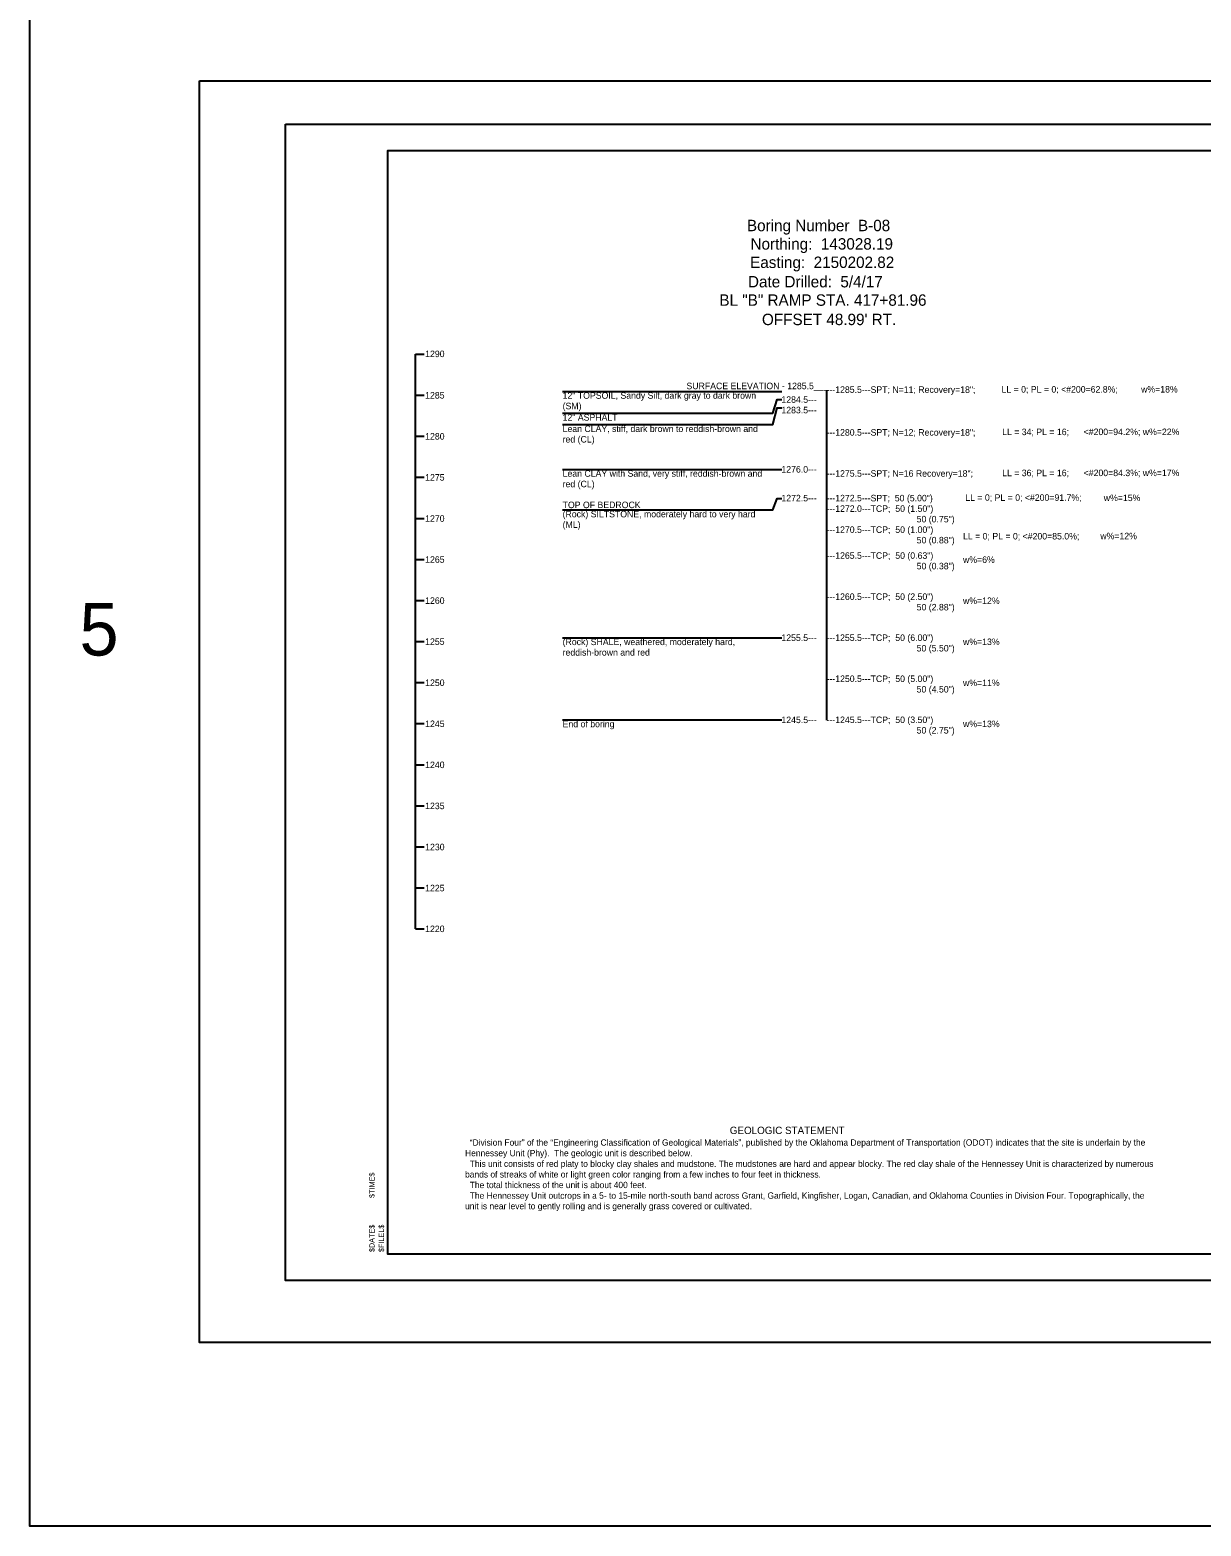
# Model space of a CAD drawing. Extents: x 2150162 to 2150245, y 143729 to 143865.
# Drawn here: x 2150161.57 to 2150183.85, y 143729.32 to 143757.78 of the extents above; entities that cross this region are included whole.
import ezdxf

# ---------------------------------------------------------------- set-up
doc = ezdxf.new("R2010")
doc.units = 0
for name, color, linetype in [('Default', 7, 'Continuous'), ('S', 7, 'Continuous'), ('SHT_Plot_Shape_Full', 7, 'Continuous'), ('SHT_Plot_Shape_Half', 7, 'Continuous'), ('SHT_Plot_Stamp', 7, 'Continuous'), ('SHT_Sheet_Border', 7, 'Continuous'), ('Text', 7, 'Continuous')]:
    doc.layers.add(name, color=color, linetype=linetype)

# ---------------------------------------------------------------- blocks, each defined once
blk = doc.blocks.new('Stamp_Plot_Stamp')
at = {"layer": 'SHT_Plot_Stamp'}
for s, p in [('$TIME$', (1.695, 1.572)), ('$DATE$', (1.695, 0.542)), ('$FILEL$', (1.873, 0.542))]:
    blk.add_text(s, height=0.1, rotation=90, dxfattribs=at).set_placement(p)

msp = doc.modelspace()

# ---------------------------------------------------------------- linework, layer by layer
at = {"layer": 'Default'}
msp.add_line((2150168.905, 143740.676), (2150168.905, 143751.613), dxfattribs=at)
for points in [[(2150168.905, 143751.613), (2150169.071, 143751.613)], [(2150176.723, 143750.929), (2150176.723, 143744.65)], [(2150168.905, 143750.832), (2150169.071, 143750.832)], [(2150171.702, 143750.904), (2150175.869, 143750.904)], [(2150171.702, 143750.487), (2150175.702, 143750.487), (2150175.785, 143750.748), (2150175.869, 143750.748)], [(2150171.702, 143750.271), (2150175.702, 143750.271), (2150175.785, 143750.592), (2150175.869, 143750.592)], [(2150168.905, 143750.051), (2150169.071, 143750.051)], [(2150168.905, 143749.27), (2150169.071, 143749.27)], [(2150168.905, 143749.27), (2150169.071, 143749.27)], [(2150171.702, 143749.42), (2150175.869, 143749.42)], [(2150171.702, 143748.647), (2150175.702, 143748.647), (2150175.785, 143748.864), (2150175.869, 143748.864)], [(2150168.905, 143748.488), (2150169.071, 143748.488)], [(2150168.905, 143747.707), (2150169.071, 143747.707)], [(2150168.905, 143746.926), (2150169.071, 143746.926)], [(2150168.905, 143746.145), (2150169.071, 143746.145)], [(2150171.702, 143746.217), (2150175.869, 143746.217)], [(2150168.905, 143745.363), (2150169.071, 143745.363)], [(2150168.905, 143744.582), (2150169.071, 143744.582)], [(2150171.702, 143744.654), (2150175.869, 143744.654)], [(2150168.905, 143743.801), (2150169.071, 143743.801)], [(2150168.905, 143743.02), (2150169.071, 143743.02)], [(2150168.905, 143742.238), (2150169.071, 143742.238)], [(2150168.905, 143741.457), (2150169.071, 143741.457)], [(2150168.905, 143740.676), (2150169.071, 143740.676)]]:
    msp.add_lwpolyline(points, dxfattribs=at)
at = {"layer": 'S'}
msp.add_lwpolyline([(2150161.568, 143784.341), (2150203.404, 143784.341), (2150203.404, 143729.315), (2150161.568, 143729.315)], close=True, dxfattribs=at)
at = {"layer": 'SHT_Plot_Shape_Full'}
msp.add_lwpolyline([(2150164.792, 143756.811), (2150200.792, 143756.811), (2150200.792, 143732.811), (2150164.792, 143732.811)], close=True, dxfattribs=at)
at = {"layer": 'SHT_Plot_Shape_Half'}
msp.add_lwpolyline([(2150166.429, 143755.986), (2150200.429, 143755.986), (2150200.429, 143733.986), (2150166.429, 143733.986)], close=True, dxfattribs=at)
at = {"layer": 'SHT_Sheet_Border'}
msp.add_lwpolyline([(2150199.879, 143734.486), (2150168.379, 143734.486), (2150168.379, 143755.486), (2150199.879, 143755.486)], close=True, dxfattribs=at)

# ---------------------------------------------------------------- block references
at = {"layer": 'SHT_Plot_Stamp'}
msp.add_blockref('Stamp_Plot_Stamp', (2150166.429, 143733.986), dxfattribs=at)

# ---------------------------------------------------------------- texts
at = {"layer": 'Default'}
for s, height, p in [('Boring Number  B-08', 0.217, (2150175.208, 143753.951)), ('Northing:  143028.19', 0.217, (2150175.276, 143753.601)), ('Easting:  2150202.82', 0.217, (2150175.268, 143753.251)), ('Date Drilled:  5/4/17', 0.217, (2150175.228, 143752.882)), ('BL "B" RAMP STA. 417+81.96', 0.217, (2150174.684, 143752.532)), ("OFFSET 48.99' RT.", 0.217, (2150175.494, 143752.164)), ('1290', 0.124, (2150169.087, 143751.555)), ('SURFACE ELEVATION - 1285.5___', 0.124, (2150174.058, 143750.945)), ('---1285.5---SPT; N=11; Recovery=18";', 0.124, (2150176.722, 143750.875)), ('LL = 0; PL = 0; <#200=62.8%;', 0.124, (2150180.051, 143750.88)), ('w%=18%', 0.124, (2150182.707, 143750.882)), ('1285', 0.124, (2150169.087, 143750.767)), ('(SM)', 0.124, (2150171.702, 143750.563)), ('12" TOPSOIL, Sandy Silt, dark gray to dark brown', 0.124, (2150171.702, 143750.763)), ('1284.5---', 0.124, (2150175.864, 143750.686)), ('12" ASPHALT', 0.124, (2150171.702, 143750.347)), ('1283.5---', 0.124, (2150175.864, 143750.486)), ('1280', 0.124, (2150169.087, 143749.986)), ('Lean CLAY, stiff, dark brown to reddish-brown and', 0.124, (2150171.702, 143750.13)), ('---1280.5---SPT; N=12; Recovery=18";', 0.124, (2150176.722, 143750.061)), ('LL = 34; PL = 16;', 0.124, (2150180.063, 143750.071)), ('<#200=94.2%; w%=22%', 0.124, (2150181.614, 143750.072)), ('red (CL)', 0.124, (2150171.702, 143749.93)), ('1275', 0.124, (2150169.087, 143749.205)), ('Lean CLAY with Sand, very stiff, reddish-brown and', 0.124, (2150171.702, 143749.279)), ('1276.0---', 0.124, (2150175.864, 143749.358)), ('---1275.5---SPT; N=16 Recovery=18";', 0.124, (2150176.722, 143749.28)), ('LL = 36; PL = 16;', 0.124, (2150180.063, 143749.29)), ('<#200=84.3%; w%=17%', 0.124, (2150181.614, 143749.291)), ('red (CL)', 0.124, (2150171.702, 143749.079)), ('1272.5---', 0.124, (2150175.864, 143748.811)), ('---1272.5---SPT;  50 (5.00")', 0.124, (2150176.722, 143748.811)), ('LL = 0; PL = 0; <#200=91.7%;', 0.124, (2150179.362, 143748.821)), ('w%=15%', 0.124, (2150181.997, 143748.816)), ('TOP OF BEDROCK', 0.124, (2150171.702, 143748.682)), ('---1272.0---TCP;  50 (1.50")', 0.124, (2150176.722, 143748.611)), ('1270', 0.124, (2150169.087, 143748.423)), ('(Rock) SILTSTONE, moderately hard to very hard', 0.124, (2150171.702, 143748.507)), ('(ML)', 0.124, (2150171.702, 143748.307)), ('50 (0.75")', 0.124, (2150178.437, 143748.411)), ('---1270.5---TCP;  50 (1.00")', 0.124, (2150176.722, 143748.211)), ('50 (0.88")', 0.124, (2150178.437, 143748.011)), ('LL = 0; PL = 0; <#200=85.0%;', 0.124, (2150179.319, 143748.086)), ('w%=12%', 0.124, (2150181.931, 143748.09)), ('---1265.5---TCP;  50 (0.63")', 0.124, (2150176.722, 143747.718)), ('1265', 0.124, (2150169.087, 143747.642)), ('50 (0.38")', 0.124, (2150178.437, 143747.518)), ('w%=6%', 0.124, (2150179.319, 143747.64)), ('1260', 0.124, (2150169.087, 143746.861)), ('---1260.5---TCP;  50 (2.50")', 0.124, (2150176.722, 143746.936)), ('w%=12%', 0.124, (2150179.319, 143746.858)), ('50 (2.88")', 0.124, (2150178.437, 143746.736)), ('1255', 0.124, (2150169.087, 143746.08)), ('(Rock) SHALE, weathered, moderately hard,', 0.124, (2150171.702, 143746.076)), ('1255.5---', 0.124, (2150175.864, 143746.155)), ('---1255.5---TCP;  50 (6.00")', 0.124, (2150176.722, 143746.155)), ('w%=13%', 0.124, (2150179.319, 143746.077)), ('reddish-brown and red', 0.124, (2150171.702, 143745.876)), ('50 (5.50")', 0.124, (2150178.437, 143745.955)), ('1250', 0.124, (2150169.087, 143745.298)), ('---1250.5---TCP;  50 (5.00")', 0.124, (2150176.722, 143745.374)), ('50 (4.50")', 0.124, (2150178.437, 143745.174)), ('w%=11%', 0.124, (2150179.319, 143745.296)), ('1245.5---', 0.124, (2150175.864, 143744.592)), ('---1245.5---TCP;  50 (3.50")', 0.124, (2150176.722, 143744.593)), ('1245', 0.124, (2150169.087, 143744.517)), ('End of boring', 0.124, (2150171.702, 143744.513)), ('50 (2.75")', 0.124, (2150178.437, 143744.393)), ('w%=13%', 0.124, (2150179.319, 143744.515)), ('1240', 0.124, (2150169.087, 143743.736)), ('1235', 0.124, (2150169.087, 143742.955)), ('1230', 0.124, (2150169.087, 143742.173)), ('1225', 0.124, (2150169.087, 143741.392)), ('1220', 0.124, (2150169.087, 143740.616))]:
    msp.add_text(s, height=height, dxfattribs=at).set_placement(p)
at = {"layer": 'S'}
msp.add_text('5', height=1, dxfattribs=at).set_placement((2150162.511, 143745.878))
at = {"layer": 'Text'}
for s, height, p in [('GEOLOGIC STATEMENT', 0.14, (2150174.882, 143736.774)), ('Hennessey Unit (Phy).  The geologic unit is described below. ', 0.12, (2150169.846, 143736.351)), ('  “Division Four” of the “Engineering Classification of Geological Materials”, published by the Oklahoma Department of Transportation (ODOT) indicates that the site is underlain by the ', 0.12, (2150169.846, 143736.553)), ('  This unit consists of red platy to blocky clay shales and mudstone. The mudstones are hard and appear blocky. The red clay shale of the Hennessey Unit is characterized by numerous ', 0.12, (2150169.846, 143736.149)), ('bands of streaks of white or light green color ranging from a few inches to four feet in thickness. ', 0.12, (2150169.846, 143735.947)), ('  The total thickness of the unit is about 400 feet.', 0.12, (2150169.846, 143735.745)), ('  The Hennessey Unit outcrops in a 5- to 15-mile north-south band across Grant, Garfield, Kingfisher, Logan, Canadian, and Oklahoma Counties in Division Four. Topographically, the ', 0.12, (2150169.846, 143735.543)), ('unit is near level to gently rolling and is generally grass covered or cultivated.', 0.12, (2150169.846, 143735.343))]:
    msp.add_text(s, height=height, dxfattribs=at).set_placement(p)

doc.saveas('drawing.dxf')
